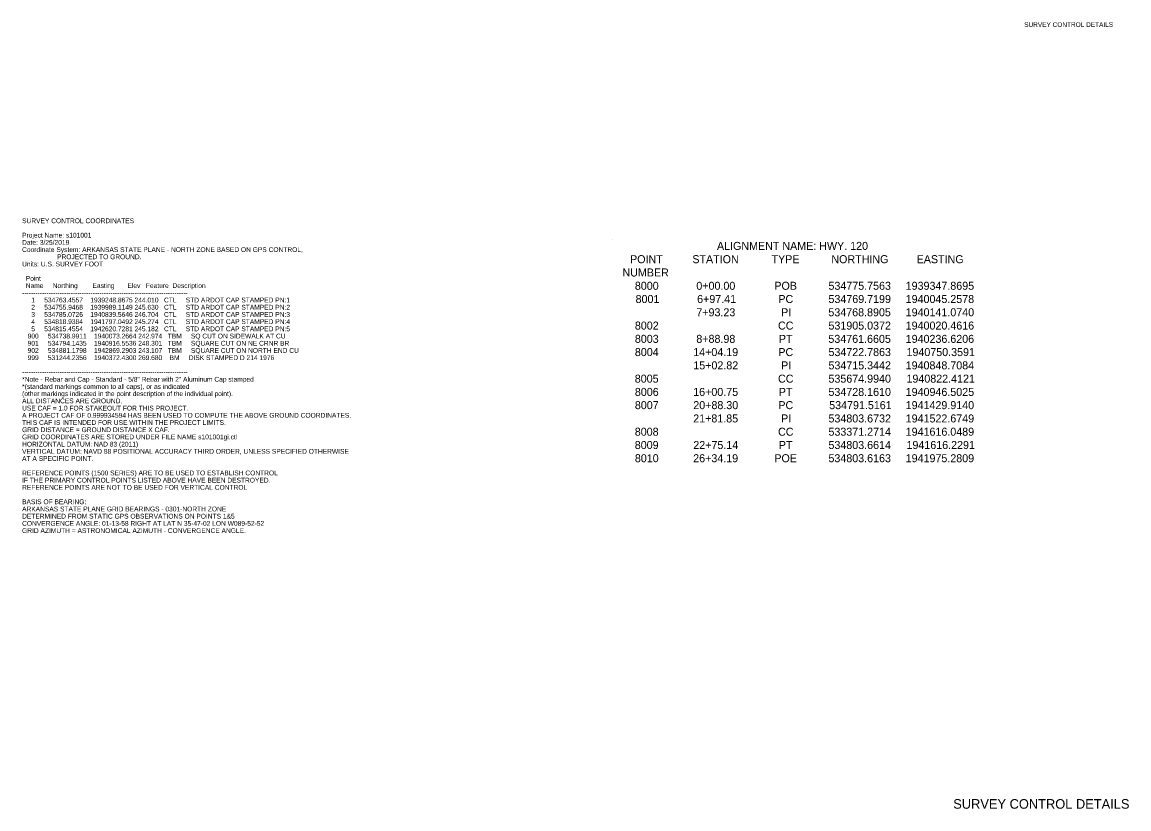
# Model space of a CAD drawing. Extents: x 1939406 to 1940789, y 534174 to 535157.
import ezdxf

# ---------------------------------------------------------------- set-up
doc = ezdxf.new("R2010")
doc.units = 0
for name, color, linetype in [('Default', 7, 'Continuous'), ('R_Annotation', 7, 'Continuous'), ('R_Border', 7, 'Continuous'), ('R_No Plot', 7, 'Continuous')]:
    doc.layers.add(name, color=color, linetype=linetype)

msp = doc.modelspace()

# ---------------------------------------------------------------- linework, layer by layer
at = {"layer": 'R_No Plot'}
msp.add_line((1940143.3, 534885.4), (1940143.3, 534885.4), dxfattribs=at)

# ---------------------------------------------------------------- texts
at = {"layer": 'Default'}
for s, height, p in [('SURVEY CONTROL COORDINATES ', 6, (1939405.8, 534905.5)), ('Project Name: s101001 ', 6, (1939405.8, 534887.5)), ('Date: 3/25/2019 ', 6, (1939405.8, 534878.5)), ('ALIGNMENT NAME: HWY. 120', 10, (1940274.1, 534872.1)), ('Coordinate System: ARKANSAS STATE PLANE - NORTH ZONE BASED ON GPS CONTROL, ', 6, (1939405.8, 534869.5)), ('                   PROJECTED TO GROUND. ', 6, (1939405.8, 534860.5)), ('POINT', 10, (1940165.5, 534855.5)), ('STATION', 10, (1940243.3, 534855.5)), ('TYPE', 10, (1940342.3, 534855.5)), ('NORTHING', 10, (1940417, 534855.5)), ('EASTING', 10, (1940523.6, 534855.5)), ('Units: U.S. SURVEY FOOT ', 6, (1939405.8, 534851.5)), ('  Point ', 6, (1939405.8, 534833.5)), ('NUMBER', 10, (1940156, 534838.9)), ('  Name     Northing        Easting       Elev   Feature  Description ', 6, (1939405.8, 534824.5)), ('8000', 10, (1940171.5, 534822.3)), ('0+00.00', 10, (1940248.3, 534822.3)), ('POB', 10, (1940345.8, 534822.3)), ('534775.7563', 10, (1940413.4, 534822.3)), ('1939347.8695', 10, (1940509.9, 534822.3)), ('--------------------------------------------------------------------------- ', 6, (1939405.8, 534815.5)), ('     1     534763.4557    1939248.8675 244.010   CTL     STD ARDOT CAP STAMPED PN:1 ', 6, (1939405.8, 534806.5)), ('8001', 10, (1940172.4, 534805.8)), ('6+97.41', 10, (1940249.3, 534805.8)), ('PC', 10, (1940350.8, 534805.8)), ('534769.7199', 10, (1940413.4, 534805.8)), ('1940045.2578', 10, (1940509.9, 534805.8)), ('     2     534755.9468    1939989.1149 245.630   CTL     STD ARDOT CAP STAMPED PN:2 ', 6, (1939405.8, 534797.5)), ('7+93.23', 10, (1940248.3, 534789.2)), ('PI', 10, (1940354.2, 534789.2)), ('534768.8905', 10, (1940413.3, 534789.2)), ('1940141.0740', 10, (1940509.9, 534789.2)), ('     4     534818.9384    1941797.0492 245.274   CTL     STD ARDOT CAP STAMPED PN:4 ', 6, (1939405.8, 534779.5)), ('     3     534785.0726    1940839.5646 246.704   CTL     STD ARDOT CAP STAMPED PN:3 ', 6, (1939405.8, 534788.5)), ('8002', 10, (1940171.5, 534772.6)), ('CC', 10, (1940350.4, 534772.6)), ('531905.0372', 10, (1940413.4, 534772.6)), ('1940020.4616', 10, (1940509.9, 534772.6)), ('   900     534738.9911    1940073.2664 242.974   TBM     SQ CUT ON SIDEWALK AT CU ', 6, (1939405.8, 534761.5)), ('     5     534815.4554    1942620.7281 245.182   CTL     STD ARDOT CAP STAMPED PN:5 ', 6, (1939405.8, 534770.5)), ('   901     534794.1435    1940916.5536 248.301   TBM     SQUARE CUT ON NE CRNR BR ', 6, (1939405.8, 534752.5)), ('8003', 10, (1940171.5, 534756)), ('8+88.98', 10, (1940248.3, 534756)), ('PT', 10, (1940351.4, 534756)), ('534761.6605', 10, (1940413.3, 534756)), ('1940236.6206', 10, (1940509.9, 534756)), ('   902     534881.1798    1942869.2903 243.107   TBM     SQUARE CUT ON NORTH END CU ', 6, (1939405.8, 534743.5)), ('   999     531244.2356    1940372.4300 269.680    BM     DISK STAMPED D 214 1976 ', 6, (1939405.8, 534734.5)), ('8004', 10, (1940171.5, 534739.5)), ('14+04.19', 10, (1940244.4, 534739.5)), ('PC', 10, (1940350.8, 534739.5)), ('534722.7863', 10, (1940413.4, 534739.5)), ('1940750.3591', 10, (1940510.9, 534739.5)), ('15+02.82', 10, (1940244.5, 534722.9)), ('PI', 10, (1940354.2, 534722.9)), ('534715.3442', 10, (1940413.4, 534722.9)), ('1940848.7084', 10, (1940509.9, 534722.9)), ('*Note - Rebar and Cap - Standard - 5/8" Rebar with 2" Aluminum Cap stamped ', 6, (1939405.8, 534707.5)), ('--------------------------------------------------------------------------- ', 6, (1939405.8, 534716.5)), ('8005', 10, (1940171.4, 534706.3)), ('CC', 10, (1940350.4, 534706.3)), ('535674.9940', 10, (1940413.4, 534706.3)), ('1940822.4121', 10, (1940510.9, 534706.3)), ('*(standard markings common to all caps), or as indicated ', 6, (1939405.8, 534698.5)), ('8006', 10, (1940171.5, 534689.7)), ('16+00.75', 10, (1940244.4, 534689.7)), ('PT', 10, (1940351.4, 534689.7)), ('534728.1610', 10, (1940413.4, 534689.7)), ('1940946.5025', 10, (1940509.9, 534689.7)), ('ALL DISTANCES ARE GROUND. ', 6, (1939405.8, 534680.5)), ('(other markings indicated in the point description of the individual point).  ', 6, (1939405.8, 534689.5)), ('USE CAF = 1.0 FOR STAKEOUT FOR THIS PROJECT. ', 6, (1939405.8, 534671.5)), ('8007', 10, (1940171.5, 534673.2)), ('20+88.30', 10, (1940244.5, 534673.2)), ('PC', 10, (1940350.8, 534673.2)), ('534791.5161', 10, (1940414.3, 534673.2)), ('1941429.9140', 10, (1940509.9, 534673.2)), ('A PROJECT CAF OF 0.999934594 HAS BEEN USED TO COMPUTE THE ABOVE GROUND COORDINATES. ', 6, (1939405.8, 534662.5)), ('THIS CAF IS INTENDED FOR USE WITHIN THE PROJECT LIMITS. ', 6, (1939405.8, 534653.5)), ('21+81.85', 10, (1940244.4, 534656.6)), ('PI', 10, (1940354.2, 534656.6)), ('534803.6732', 10, (1940413.4, 534656.6)), ('1941522.6749', 10, (1940509.9, 534656.6)), ('GRID DISTANCE = GROUND DISTANCE X CAF. ', 6, (1939405.8, 534644.5)), ('8008', 10, (1940171.4, 534640)), ('CC', 10, (1940350.4, 534640)), ('533371.2714', 10, (1940413.4, 534640)), ('1941616.0489', 10, (1940509.9, 534640)), ('GRID COORDINATES ARE STORED UNDER FILE NAME s101001gi.ctl', 6, (1939405.8, 534635.5)), ('HORIZONTAL DATUM: NAD 83 (2011) ', 6, (1939405.8, 534626.5)), ('8009', 10, (1940171.4, 534623.4)), ('22+75.14', 10, (1940244.5, 534623.4)), ('PT', 10, (1940351.4, 534623.4)), ('534803.6614', 10, (1940413.4, 534623.4)), ('1941616.2291', 10, (1940510.9, 534623.4)), ('VERTICAL DATUM: NAVD 88 POSITIONAL ACCURACY THIRD ORDER, UNLESS SPECIFIED OTHERWISE  ', 6, (1939405.8, 534617.5)), ('8010', 10, (1940171.5, 534606.9)), ('26+34.19', 10, (1940244.4, 534606.9)), ('POE', 10, (1940345.8, 534606.9)), ('534803.6163', 10, (1940413.4, 534606.9)), ('1941975.2809', 10, (1940509.9, 534606.9)), ('AT A SPECIFIC POINT. ', 6, (1939405.8, 534608.5)), ('REFERENCE POINTS (1500 SERIES) ARE TO BE USED TO ESTABLISH CONTROL ', 6, (1939405.8, 534590.5)), ('IF THE PRIMARY CONTROL POINTS LISTED ABOVE HAVE BEEN DESTROYED. ', 6, (1939405.8, 534581.5)), ('REFERENCE POINTS ARE NOT TO BE USED FOR VERTICAL CONTROL ', 6, (1939405.8, 534572.5)), ('BASIS OF BEARING: ', 6, (1939405.8, 534554.5)), ('ARKANSAS STATE PLANE GRID BEARINGS - 0301-NORTH ZONE', 6, (1939405.8, 534545.5)), ('CONVERGENCE ANGLE: 01-13-58 RIGHT AT LAT N 35-47-02 LON W089-52-52 ', 6, (1939405.8, 534527.5)), ('DETERMINED FROM STATIC GPS OBSERVATIONS ON POINTS 1&5 ', 6, (1939405.8, 534536.5)), ('GRID AZIMUTH = ASTRONOMICAL AZIMUTH - CONVERGENCE ANGLE. ', 6, (1939405.8, 534518.5))]:
    msp.add_text(s, height=height, dxfattribs=at).set_placement(p)
at = {"layer": 'R_Annotation'}
msp.add_text('SURVEY CONTROL DETAILS', height=12, dxfattribs=at).set_placement((1940569.3, 534174.1))
at = {"layer": 'R_Border'}
msp.add_text('SURVEY CONTROL DETAILS', height=5.862, dxfattribs=at).set_placement((1940658, 535150.6))

doc.saveas('drawing.dxf')
